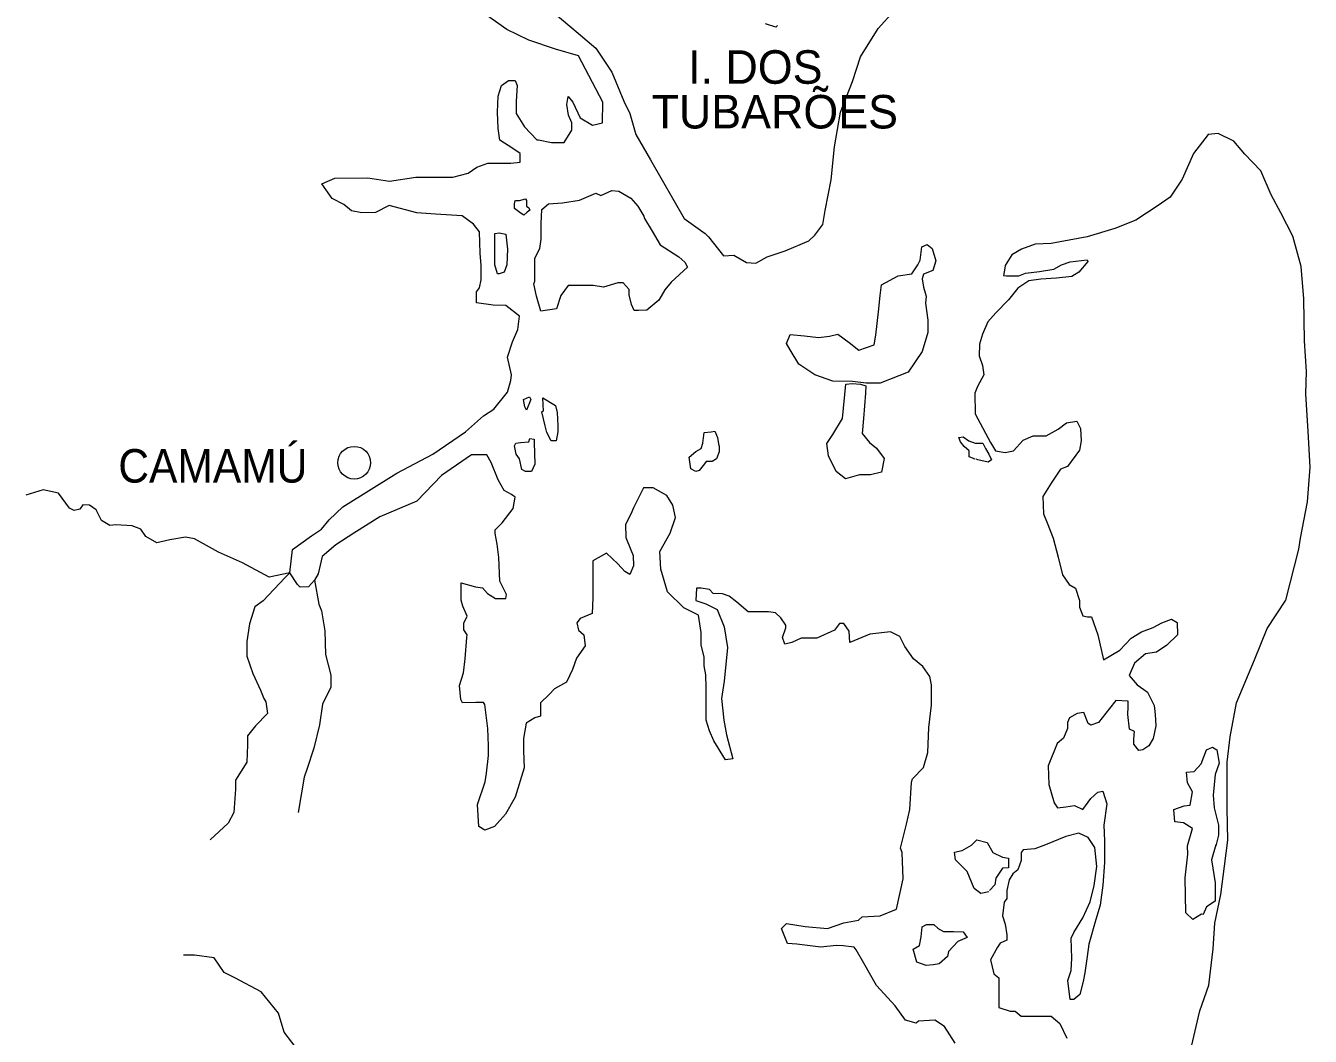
# Model space of a CAD drawing. Extents: x 47169 to 972804, y 7447977 to 9608469.
# Drawn here: x 482265 to 507693, y 8447860 to 8467863 of the extents above; entities that cross this region are included whole.
import ezdxf

# ---------------------------------------------------------------- set-up
doc = ezdxf.new("R2010")
doc.units = 0
doc.header["$LTSCALE"] = 270
doc.layers.add('1', color=7, linetype='Continuous', lineweight=13)
doc.layers.add('2', color=7, linetype='Continuous', lineweight=13)
doc.layers.add('3', color=7, linetype='Continuous')

msp = doc.modelspace()

# ---------------------------------------------------------------- linework, layer by layer
at = {"layer": '1'}
for points in [[(492545.5, 8468261.4), (493075.1, 8467819.1), (493550.7, 8467421.1), (493864.1, 8466945.6), (494102, 8466370.6), (494220.9, 8466127.3), (494339.9, 8465707.1), (494631.7, 8465209.4), (495301.8, 8464048.3), (495712.5, 8463749.8), (495777.3, 8463683.4), (496079.9, 8463307.4), (496285.1, 8463318.6), (496533.7, 8463174.8), (496717.3, 8463163.8), (496944.2, 8463285.5), (497300.7, 8463407.2), (497765.3, 8463606.3), (497884.1, 8463716.9), (498046.2, 8463927), (498089.4, 8464203.5), (498208.2, 8464811.8), (498273, 8465464.3), (498391.8, 8466150), (498629.5, 8466758.3), (498791.5, 8467244.9), (499137.3, 8467809), (499450.7, 8468151.8)], [(491973.4, 8466126.7), (492135.6, 8465861.3), (492384.2, 8465607), (492416.6, 8465607), (492675.9, 8465551.8), (492924.4, 8465551.9), (493075.6, 8465795.2), (493075.6, 8465939), (493010.7, 8466093.8), (492978.2, 8466303.9), (492999.8, 8466458.8), (493097.1, 8466348.2), (493237.7, 8466038.6), (493486.2, 8465894.9), (493680.7, 8465939.2), (493691.4, 8466348.4), (493204.9, 8467266.2), (492751, 8467398.8), (492221.5, 8467575.6), (491789.2, 8467785.6), (491389.3, 8468073)], [(497149, 8467864.1), (497116.6, 8467831), (496911.2, 8467897.3)], [(490993.7, 8455752.5), (491004.5, 8455807.8), (490939.7, 8455907.3), (490939.6, 8456040), (491004.4, 8456172.7), (490917.9, 8456371.8), (490885.5, 8456493.4), (490885.4, 8456836.3), (491166.2, 8456758.9), (491306.6, 8456736.9), (491403.9, 8456626.3), (491565.9, 8456526.8), (491771.2, 8456526.9), (491782, 8456604.3), (491652.2, 8456869.7), (491630.5, 8457334.2), (491598, 8457599.6), (491554.7, 8457809.7), (491554.7, 8457887.2), (491695.1, 8458019.9), (491911, 8458307.6), (491954.2, 8458528.8), (491878.5, 8458584), (491738.1, 8458661.4), (491619.2, 8458871.5), (491478.6, 8459214.3), (491392.2, 8459369.1), (491089.7, 8459369), (490495.7, 8458959.6), (490009.8, 8458450.7), (489275.4, 8458140.7), (488757, 8457819.7), (488400.7, 8457587.3), (488130.7, 8457354.9), (488055.3, 8457012.1), (487979.7, 8456890.4), (487861, 8456757.6), (487699, 8456746.5), (487644.9, 8456801.7), (487493.6, 8457033.9), (487547.4, 8457498.4), (487925.3, 8457764.1), (488119.7, 8457896.9), (488270.8, 8458084.9), (488540.8, 8458339.4), (489609.9, 8459003.5), (490322.7, 8459379.8), (490970.7, 8459822.4), (491327.1, 8460143.2), (491532.3, 8460276), (491802.3, 8460607.9), (491867, 8460840.2), (491877.8, 8460950.8), (491802, 8461304.7), (491899.2, 8461603.3), (492007.1, 8461846.7), (492039.5, 8462112.1), (491769.3, 8462322.1), (491520.8, 8462333.1), (491185.9, 8462377.2), (491185.8, 8462598.4), (491250.6, 8462675.9), (491283, 8462830.7), (491282.9, 8463051.9), (491282.9, 8463118.3), (491261.2, 8463361.6), (491250.2, 8463781.8), (491131.3, 8463936.6), (490904.4, 8464102.4), (490375, 8464135.4), (490007.6, 8464157.4), (489456.5, 8464301), (489186.4, 8464168.1), (488916.3, 8464157), (488711, 8464201.1), (488559.7, 8464322.7), (488332.8, 8464444.3), (488127.3, 8464731.7), (488386.6, 8464842.4), (489034.9, 8464853.8), (489467.1, 8464787.6), (489985.7, 8464865.2), (490720.4, 8464865.5), (491022.9, 8464943), (491195.8, 8465064.7), (491411.9, 8465142.2), (491552.3, 8465142.3), (491865.7, 8465142.4), (492049.3, 8465164.5), (492049.3, 8465330.4), (491908.8, 8465429.9), (491649.4, 8465595.7), (491616.9, 8465828), (491606, 8466148.7), (491616.7, 8466469.4), (491681.5, 8466679.6), (491821.9, 8466779.2), (491951.6, 8466779.2), (491994.8, 8466679.7), (491973.3, 8466370), (491973.4, 8466126.7)], [(505292.6, 8447458.7), (505508.7, 8448365.6), (505681.6, 8448874.3), (505768.1, 8449593.2), (505800.7, 8450101.9), (505919.6, 8450665.9), (505995.3, 8451229.9), (506060.2, 8451738.7), (506049.6, 8452369.1), (506049.7, 8452944.2), (506049.8, 8453287), (506103.9, 8453784.7), (506233.7, 8454459.3), (506590.3, 8455310.8), (506838.9, 8455930.1), (507206.3, 8456494), (507465.8, 8457500.4), (507498.3, 8457721.6), (507638.9, 8458440.4), (507693.1, 8459126.1), (507650.1, 8459833.9), (507607.1, 8460574.9), (507618.1, 8461017.3), (507575, 8461625.6), (507564.5, 8462455.1), (507510.6, 8463096.5), (507348.8, 8463693.8), (507111.2, 8464158.4), (506916.8, 8464512.3), (506711.6, 8464987.9), (506398.4, 8465319.8), (506182.3, 8465574.2), (505869, 8465729.1), (505674.5, 8465707.1), (505382.7, 8465331.1), (505155.7, 8464822.4), (504917.9, 8464468.5), (504658.6, 8464291.6), (504237.2, 8464015.2), (503826.5, 8463849.4), (503275.5, 8463683.6), (502562.4, 8463550.9), (502249.1, 8463539.9), (501979, 8463440.4), (501784.5, 8463329.8), (501654.8, 8463119.7), (501644, 8463064.4), (501622.4, 8462920.6), (501676.4, 8462909.6), (501924.9, 8462909.5), (502054.6, 8462964.8), (502335.5, 8462998), (502616.4, 8463042.2), (502767.6, 8463130.7), (502940.5, 8463185.9), (503275.5, 8463230.1), (503286.2, 8463196.9), (503113.4, 8462986.8), (502972.9, 8462898.4), (502670.4, 8462865.2), (502357.1, 8462843.2), (502119.4, 8462810), (501903.3, 8462666.2), (501719.6, 8462434), (501471.1, 8462179.6), (501309, 8462002.7), (501201, 8461759.4), (501147, 8461560.3), (501136.1, 8461328.1), (501201, 8461140.1), (501233.4, 8460952), (501103.7, 8460719.8), (501049.7, 8460587.1), (501060.5, 8460177.9), (501362.9, 8459613.8), (501460.1, 8459447.9), (501654.6, 8459414.7), (501816.6, 8459447.9), (502011.1, 8459658), (502205.5, 8459746.5), (502464.8, 8459746.4), (502702.5, 8459879.2), (502864.5, 8460000.8), (503069.8, 8460033.9), (503145.4, 8459890.2), (503156.2, 8459646.8), (503123.7, 8459458.8), (502886, 8459138.1), (502745.6, 8459082.8)], [(491963.1, 8464401.4), (492038.8, 8464401.4), (492157.6, 8464434.6), (492179.2, 8464401.5), (492179.3, 8464290.9), (492222.5, 8464257.7), (492244.1, 8464213.5), (492190.1, 8464169.2), (492125.3, 8464113.9), (492071.3, 8464147.1), (491941.6, 8464246.6), (491941.5, 8464335), (491952.3, 8464401.4)], [(492515.4, 8460232.1), (492504.5, 8460497.5), (492753, 8460342.8), (492785.5, 8460210.1), (492796.3, 8459944.6), (492796.4, 8459823), (492764, 8459646), (492666.8, 8459646), (492580.3, 8459811.9), (492547.9, 8459944.6), (492483, 8460221), (492515.4, 8460243.2)], [(495994, 8459547.2), (495994, 8459425.5), (495940, 8459292.8), (495853.6, 8459237.5), (495734.8, 8459237.5), (495702.4, 8459193.2), (495594.4, 8459060.5), (495529.6, 8459038.4), (495432.4, 8459093.7), (495399.9, 8459325.9), (495529.5, 8459436.5), (495637.5, 8459491.8), (495669.9, 8459602.4), (495691.5, 8459812.6), (495831.9, 8459823.7), (495907.5, 8459834.7), (495961.6, 8459713.1), (495983.2, 8459547.2)], [(501060.4, 8459282.1), (500941.6, 8459326.3), (500941.6, 8459447.9), (500844.4, 8459536.4), (500768.8, 8459624.9), (500736.4, 8459713.4), (500822.8, 8459724.4), (500930.8, 8459647), (501060.5, 8459602.8), (501211.7, 8459602.8), (501265.7, 8459492.2), (501330.5, 8459381.6), (501384.5, 8459271), (501319.7, 8459226.7), (501114.5, 8459271), (501082, 8459282.1)], [(502745.6, 8459082.8), (502561.9, 8458806.4), (502399.9, 8458540.9), (502410.7, 8458198.1), (502486.2, 8458021.2), (502605, 8457722.5), (502702.2, 8457346.5), (502788.6, 8456992.6), (502918.2, 8456804.6), (503047.8, 8456727.1), (503123.4, 8456483.8), (503123.4, 8456351.1), (503188.2, 8456185.2), (503285.3, 8456163), (503361, 8456163), (503490.5, 8455809.1), (503598.5, 8455311.4), (503922.5, 8455499.4), (504149.4, 8455742.7), (504354.6, 8455864.3), (504581.5, 8455952.7), (504754.3, 8456041.2), (504948.7, 8456118.5), (505056.7, 8456052.2), (505067.5, 8455808.8), (504851.4, 8455598.8), (504646.2, 8455466.1), (504430.2, 8455432.9), (504214.1, 8455245), (504106.1, 8455001.7), (504268, 8454813.6), (504397.6, 8454725.1), (504473.2, 8454669.8), (504602.8, 8454404.4), (504624.3, 8454227.4), (504635.1, 8454006.2), (504581.1, 8453751.8), (504494.6, 8453608.1), (504375.8, 8453530.7), (504300.2, 8453519.6), (504203, 8453641.3), (504203, 8453740.8), (504213.9, 8453895.7), (504116.7, 8453939.9), (504084.3, 8454227.5), (504084.4, 8454382.3), (504084.4, 8454492.9), (503846.8, 8454504), (503717.1, 8454349.2), (503501.1, 8454072.7), (503349.9, 8454017.5), (503295.9, 8454050.6), (503209.5, 8454271.8), (503079.9, 8454249.8), (502928.7, 8454161.3), (502885.5, 8454072.8), (502885.5, 8453951.2), (502809.8, 8453763.2), (502680.2, 8453652.6), (502507.4, 8453210.2), (502518.1, 8452845.2), (502626.1, 8452480.2), (502690.9, 8452380.7), (502852.9, 8452402.8), (503025.7, 8452424.9), (503187.7, 8452347.5), (503349.7, 8452568.6), (503490.1, 8452690.3), (503587.3, 8452712.4), (503662.9, 8452458), (503608.8, 8452037.7), (503619.6, 8451728.1), (503619.5, 8451296.8), (503587, 8450854.4), (503533, 8450456.2), (503446.6, 8450168.7), (503306.1, 8449682.1), (503273.7, 8449438.8), (503230.5, 8449118), (503198, 8448941.1), (503133.2, 8448686.7), (503014.4, 8448587.2), (502938.8, 8448587.2), (502895.7, 8448963.2), (502960.5, 8449162.3), (502971.3, 8449405.6), (502960.6, 8449803.8), (503014.6, 8449914.4), (503187.4, 8450201.9), (503338.6, 8450522.6), (503414.2, 8450843.3), (503468.3, 8451219.3), (503425.2, 8451595.4), (503295.6, 8451794.5), (503112, 8451883), (502852.8, 8451816.6), (502453.2, 8451650.8), (502237.2, 8451573.4), (502010.5, 8451551.3), (501967.2, 8451496), (501967.2, 8451341.2)], [(487493.6, 8457033.9), (487083.2, 8456945.2), (486553.7, 8457232.5), (486078.4, 8457442.4), (485602.9, 8457707.6), (485430.1, 8457740.6), (485116.9, 8457685.2), (484857.7, 8457629.7), (484641.5, 8457751.2), (484544.2, 8457895), (484371.4, 8457961.2), (484047.3, 8457983.1), (483928.5, 8457972), (483766.4, 8458071.4), (483658.2, 8458281.5), (483528.5, 8458369.9), (483398.9, 8458380.9), (483334.2, 8458292.3), (483226.2, 8458270.2), (483128.9, 8458314.3), (482912.7, 8458612.8), (482610.2, 8458678.9), (482264.6, 8458568.1)], [(497290.8, 8455621.2), (497247.5, 8455753.9), (497312.3, 8455941.9), (497312.3, 8455997.2), (497215.1, 8456141), (497107.1, 8456240.5), (496966.6, 8456262.6), (496891, 8456262.6), (496761.4, 8456262.6), (496567, 8456262.6), (496340.2, 8456450.5), (496188.9, 8456572.2), (496059.3, 8456616.4), (495875.7, 8456627.4), (495800, 8456704.8), (495638, 8456726.9), (495540.8, 8456726.9), (495530, 8456483.6), (495724.5, 8456417.3), (495951.3, 8456306.7), (496091.8, 8455963.9), (496156.7, 8455554.7), (496092, 8454891.1), (496038, 8454548.2), (496081.3, 8454116.9), (496135.3, 8453829.4), (496265, 8453353.8), (496113.8, 8453331.7), (495886.9, 8453707.7), (495800.5, 8453906.7), (495735.7, 8454116.9), (495735.6, 8454548.2), (495735.6, 8454758.3), (495724.7, 8455012.7), (495692.3, 8455189.6), (495692.3, 8455366.6), (495638.2, 8455609.9), (495638.2, 8455853.2), (495584.1, 8456196.1), (495292.5, 8456339.8), (494968.3, 8456660.4), (494838.6, 8457102.8), (494817, 8457456.7), (495022.1, 8457821.7), (495130.1, 8458131.4), (495076, 8458374.7), (494957.2, 8458562.7), (494687.1, 8458717.5), (494492.6, 8458717.4), (494298.3, 8458319.2), (494244.3, 8458197.6), (494136.3, 8457987.4), (494147.2, 8457733.1), (494244.5, 8457489.8), (494287.7, 8457379.2), (494298.5, 8457169), (494223, 8457003.1), (494125.7, 8457058.4), (493985.3, 8457213.2), (493758.4, 8457423.3), (493488.4, 8457268.4), (493488.5, 8456859.2), (493488.6, 8456538.4), (493477.9, 8456228.8), (493240.3, 8456129.2), (493175.5, 8456040.7), (493207.9, 8455896.9), (493316, 8455808.5), (493337.6, 8455587.3), (493164.9, 8455343.9), (493089.3, 8455122.7), (492970.6, 8454868.3), (492733, 8454735.5), (492625, 8454624.9), (492452.3, 8454459), (492452.3, 8454193.5), (492344.4, 8454160.3), (492171.6, 8454060.7), (492117.7, 8453751), (492117.7, 8453507.7), (492128.6, 8453175.9), (491956, 8452589.7), (491761.7, 8452257.9), (491545.8, 8452014.5), (491351.5, 8451937), (491232.6, 8452014.4), (491210.9, 8452445.7), (491361.9, 8452899.2), (491383.5, 8453065.1), (491426.6, 8453419), (491426.5, 8453607), (491415.6, 8453949.9), (491350.6, 8454425.4), (491329, 8454469.7), (491177.8, 8454469.6), (490907.8, 8454458.4), (490875.4, 8454524.8), (490853.7, 8454801.3), (490929.2, 8455055.7), (490961.5, 8455332.2), (490993.7, 8455752.5)], [(487493.6, 8457033.9), (487396.4, 8456934.3), (486964.6, 8456480.7), (486802.6, 8456358.9), (486694.8, 8456027.1), (486641, 8455673.1), (486641.1, 8455385.6), (486760.1, 8455042.8), (486911.5, 8454711.1), (486976.4, 8454545.2), (487019.6, 8454478.9), (487052.1, 8454246.7), (486814.6, 8454003.2), (486652.7, 8453804.1), (486652.8, 8453627.1), (486642.2, 8453284.2), (486415.6, 8452930.2), (486415.7, 8452753.3), (486383.5, 8452288.7), (486275.7, 8452078.6), (485919.5, 8451746.6)], [(487979.7, 8456890.4), (488066.4, 8456414.8), (488120.4, 8456282.2), (488185.4, 8455884), (488196.4, 8455419.5), (488304.6, 8455010.4), (488304.7, 8454767.1), (488142.9, 8454435.2), (488078.3, 8454026), (487970.5, 8453561.4), (487830.3, 8453141.1), (487776.4, 8452986.2), (487657.9, 8452289.4)], [(500660.4, 8447724.7), (500455.3, 8448056.5), (500260.9, 8448178.2), (499937, 8448156), (499893.8, 8448122.9), (499677.9, 8448178.2), (499472.7, 8448465.7), (499105.5, 8448863.9), (498857.2, 8449306.2), (498706, 8449571.7), (498662.8, 8449626.9), (498446.8, 8449649.1), (498306.4, 8449660.1), (498004.1, 8449626.9), (497528.9, 8449682.2), (497345.4, 8449693.2), (497226.5, 8449991.8), (497323.7, 8450091.4), (497690.9, 8450036.1), (498133.6, 8449991.9), (498457.6, 8450102.5), (498749.1, 8450157.8), (498824.7, 8450224.2), (499181.1, 8450246.3), (499505, 8450379), (499634.6, 8450976.3), (499613, 8451496.1), (499580.6, 8451584.6), (499667, 8451927.4), (499699.4, 8452060.1), (499764.2, 8452347.7), (499796.6, 8452889.6), (499818.2, 8452955.9), (500034.2, 8453177.2), (500120.6, 8453475.8), (500142.2, 8453973.4), (500196.2, 8454415.8), (500196.2, 8454780.8), (500196.2, 8454814), (500163.8, 8454979.9), (500023.4, 8455178.9), (499839.8, 8455333.8), (499667, 8455577.1), (499569.8, 8455776.2), (499386.1, 8455864.6), (498975.7, 8455820.4), (498576.1, 8455654.5), (498565.2, 8455875.7), (498457.2, 8456030.5), (498370.8, 8456030.5), (498273.6, 8455897.8), (497928, 8455742.9), (497614.8, 8455742.9), (497431.2, 8455654.4), (497290.8, 8455621.2)], [(505822.6, 8451650.2), (505736.1, 8451351.7), (505811.6, 8450898.2), (505811.5, 8450533.2), (505638.7, 8450422.7), (505573.9, 8450267.8), (505541.5, 8450278.9), (505368.7, 8450168.3), (505228.4, 8450301.1), (505217.7, 8450997.8), (505271.8, 8451462.4), (505261, 8451628.2), (505358.3, 8451971.1), (505185.5, 8452081.7), (505012.7, 8452103.9), (504991.2, 8452347.2), (505196.4, 8452424.6), (505315.2, 8452435.6), (505358.5, 8452701), (505261.3, 8452878), (505239.7, 8453088.1), (505390.9, 8453099.2), (505531.4, 8453254), (505639.4, 8453530.4), (505758.2, 8453585.7), (505844.6, 8453530.4), (505887.8, 8453264.9), (505812.1, 8453043.8), (505768.8, 8452634.6), (505790.4, 8452380.2), (505876.7, 8452037.3), (505876.6, 8451838.2), (505822.6, 8451628.1)], [(501330.1, 8450721.9), (501168.1, 8450688.7), (501038.5, 8450788.2), (500898.1, 8451120), (500671.3, 8451352.3), (500649.8, 8451507.1), (500800.9, 8451540.3), (500984.5, 8451639.8), (501092.5, 8451750.4), (501297.7, 8451695.1), (501405.7, 8451496), (501600.1, 8451407.6), (501718.9, 8451385.4), (501718.8, 8451197.4), (501600, 8451186.4), (501470.5, 8450987.3), (501448.9, 8450854.6), (501340.9, 8450744)], [(501967.2, 8451341.2), (501902.4, 8451153.2), (501805.2, 8451075.7), (501729.6, 8450954.1), (501686.4, 8450744), (501686.4, 8450589.1), (501632.4, 8450511.7), (501600, 8450246.3), (501654, 8450080.4), (501686.4, 8449870.2), (501686.4, 8449759.7), (501556.8, 8449704.4), (501502.8, 8449626.9), (501362.4, 8449372.6), (501427.2, 8449096.1), (501524.3, 8449018.7), (501524.3, 8448885.9), (501524.3, 8448709), (501524.3, 8448543.1), (501524.3, 8448432.5), (501751, 8448355.1), (501848.2, 8448355.1), (501967, 8448255.5), (502236.9, 8448255.5), (502560.9, 8448255.5), (502733.6, 8448111.7), (502874, 8447824.1)], [(500315, 8450003), (500433.7, 8449936.7), (500628.1, 8449936.7), (500822.5, 8449925.6), (500898.1, 8449815), (500714.5, 8449737.6), (500530.9, 8449538.5), (500509.3, 8449439), (500347.3, 8449295.2), (500228.6, 8449273.1), (500088.2, 8449262), (499904.6, 8449328.4), (499829, 8449582.8), (499958.6, 8449660.2), (499991, 8449826.1), (500012.6, 8450025.1), (500099, 8450069.4), (500239.4, 8450069.4), (500325.7, 8449992)], [(489724, 8443984.4), (489777.9, 8444095.1), (489734.6, 8444471.1), (489637.1, 8445145.7), (489431.8, 8445576.9), (489053.8, 8445842.2), (488708.2, 8446173.8), (488459.5, 8446815.2), (488146.2, 8447235.3), (487681.8, 8447544.8), (487379.2, 8447942.8), (487271.1, 8448318.8), (486925.4, 8448738.9), (486406.9, 8449015.1), (486190.9, 8449125.6), (485996.3, 8449413), (485607.6, 8449468.1), (485391.6, 8449468)]]:
    msp.add_lwpolyline(points, dxfattribs=at)
for points in [[(493648.6, 8464501.4), (493864.7, 8464601), (494005.2, 8464590), (494242.9, 8464446.2), (494383.4, 8464291.4), (494502.3, 8464092.4), (494513.1, 8464048.2), (494664.4, 8463793.8), (494826.5, 8463528.4), (495193.9, 8463285.2), (495312.8, 8463185.7), (495366.8, 8463086.1), (495042.8, 8462787.5), (494913.2, 8462632.6), (494794.4, 8462433.5), (494556.7, 8462234.4), (494394.7, 8462223.3), (494308.2, 8462223.3), (494254.2, 8462344.9), (494210.9, 8462532.9), (494210.9, 8462643.5), (494092, 8462776.2), (493984, 8462776.2), (493703.1, 8462687.7), (493497.8, 8462720.8), (493162.9, 8462720.7), (493000.8, 8462720.7), (492860.4, 8462521.5), (492774.1, 8462256.1), (492460.8, 8462211.8), (492374.3, 8462510.3), (492320.2, 8462753.6), (492341.8, 8462808.9), (492341.6, 8463262.4), (492438.8, 8463450.4), (492471.2, 8463638.4), (492471.1, 8463782.2), (492471.1, 8463948.1), (492481.8, 8464224.6), (492611.4, 8464335.2), (492892.4, 8464357.4), (493227.3, 8464412.8), (493551.4, 8464545.6)], [(491790.7, 8463129.5), (491736.7, 8462985.7), (491639.5, 8462952.5), (491607, 8462952.5), (491553, 8463129.4), (491552.8, 8463582.9), (491552.8, 8463748.8), (491639.2, 8463759.8), (491768.9, 8463737.8), (491801.4, 8463439.2)], [(498899.9, 8460786.1), (498629.8, 8460819.3), (498240.9, 8460830.3), (497884.4, 8460952), (497571, 8461162.1), (497398.2, 8461449.6), (497322.5, 8461571.3), (497398.1, 8461748.2), (497679, 8461726.1), (497959.9, 8461693), (498176, 8461715.1), (498338, 8461759.4), (498564.9, 8461593.5), (498759.4, 8461438.7), (499061.9, 8461549.3), (499094.3, 8461737.3), (499148.3, 8462201.8), (499180.7, 8462522.5), (499202.3, 8462732.7), (499537.2, 8462909.6), (499807.3, 8462953.9), (499926.2, 8463130.8), (499969.4, 8463219.3), (500001.8, 8463484.7), (500109.8, 8463528.9), (500207.1, 8463451.5), (500282.7, 8463208.2), (500217.9, 8463020.2), (500034.2, 8462942.8), (500012.6, 8462854.3), (500034.2, 8462688.4), (500066.6, 8462577.8), (500088.2, 8462511.5), (500077.4, 8462367.7), (500120.6, 8462035.9), (500120.6, 8461792.6), (500012.6, 8461416.6), (499731.7, 8461007.4), (499180.8, 8460786.2)], [(498622, 8460783.7), (498789.2, 8460766.5), (498896.9, 8460731.7), (498889.1, 8460587.1), (498845.9, 8460089.4), (498824.3, 8459790.8), (498964.7, 8459613.8), (499105.2, 8459503.2), (499256.4, 8459293.1), (499202.4, 8459027.7), (498986.4, 8458972.4), (498770.3, 8458972.4), (498489.5, 8458894.9), (498305.8, 8459038.7), (498154.6, 8459348.3), (498122.1, 8459591.7), (498241, 8459768.6), (498435.4, 8460089.4), (498501.6, 8460766.5)], [(492266.8, 8460464.3), (492180.5, 8460254.1), (492148, 8460320.5), (492115.6, 8460464.2), (492234.4, 8460519.6)], [(492342.9, 8459181.4), (492278.1, 8459037.6), (492159.2, 8459037.6), (492083.6, 8459081.8), (492040.4, 8459291.9), (491975.5, 8459380.3), (491943, 8459546.2), (491964.6, 8459601.5), (492061.9, 8459612.6), (492223.9, 8459623.7), (492245.5, 8459690.1), (492331.9, 8459679.1), (492331.9, 8459612.7)]]:
    msp.add_lwpolyline(points, close=True, dxfattribs=at)
at = {"layer": '2'}
msp.add_circle((488767.2, 8459213.2), 323.8, dxfattribs=at)

# ---------------------------------------------------------------- texts
at = {"layer": '3'}
for s, p in [('I. DOS', (495377, 8466713.7)), ('TUBARÕES', (494653.2, 8465828.8))]:
    msp.add_text(s, height=663.2, dxfattribs=at).set_placement(p)
at = {"layer": '3', "width": 0.95}
msp.add_text('CAMAMÚ', height=663, dxfattribs=at).set_placement((484097.9, 8458819.1))

doc.saveas('drawing.dxf')
